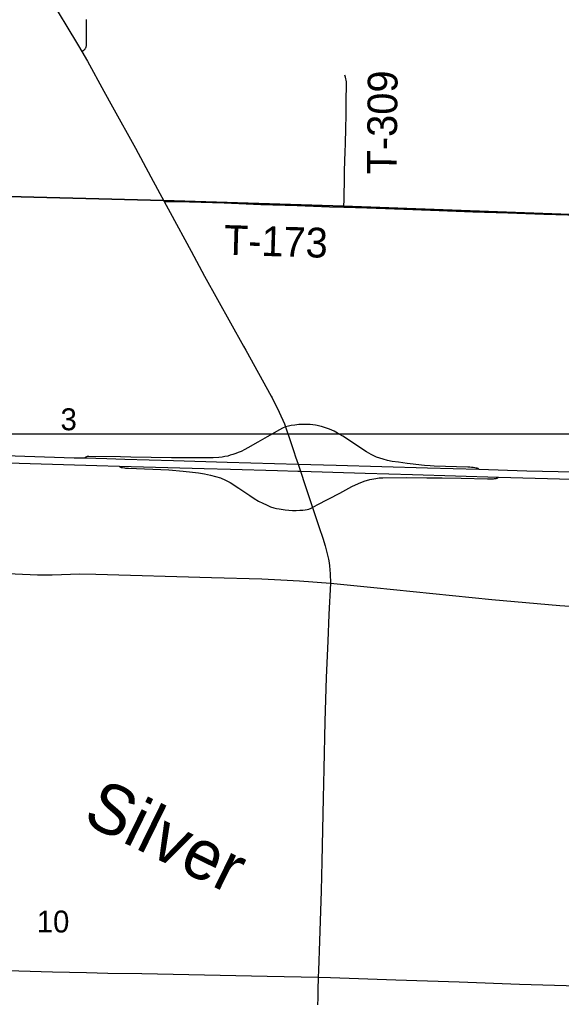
# Model space of a CAD drawing. Extents: x 0 to 68, y 0 to 52.9.
# Drawn here: x 62.532 to 65.265, y 40.611 to 45.541 of the extents above; entities that cross this region are included whole.
import ezdxf

# ---------------------------------------------------------------- set-up
doc = ezdxf.new("R2010")
doc.units = 0
for name, color, linetype in [('Default', 7, 'Continuous'), ('GM_X_County_Road', 7, 'Continuous'), ('GM_X_Minor_River_Text', 7, 'Continuous'), ('GM_X_State_Route', 7, 'Continuous'), ('GM_X_Township', 7, 'Continuous'), ('GM_X_Township_Road', 7, 'Continuous'), ('GM_X_Township_Road_Text', 7, 'Continuous')]:
    doc.layers.add(name, color=color, linetype=linetype)

msp = doc.modelspace()

# ---------------------------------------------------------------- linework, layer by layer
at = {"layer": 'Default'}
msp.add_line((49.5172, 43.4514), (67.9972, 43.4514), dxfattribs=at)
for points in [[(63.8738, 43.4876), (63.8583, 43.4805), (63.8433, 43.4728), (63.7811, 43.4371), (63.7335, 43.4098), (63.6832, 43.3813), (63.6682, 43.3733), (63.6493, 43.3636), (63.6351, 43.3574), (63.623, 43.3524), (63.608, 43.3474), (63.595, 43.3438), (63.582, 43.3403), (63.5676, 43.3372), (63.5537, 43.3347), (63.5369, 43.3327), (63.5077, 43.3308), (63.4405, 43.3305), (63.2985, 43.3315), (63.0932, 43.3352), (63.0407, 43.3361), (62.8818, 43.338), (62.8798, 43.3379), (62.8778, 43.3377), (62.8758, 43.3375), (62.8736, 43.3372), (62.8711, 43.3365), (62.8696, 43.336), (62.8683, 43.3353), (62.8666, 43.3345), (62.8649, 43.3336), (62.8632, 43.3322), (62.862, 43.3306)], [(64.8484, 43.2734), (64.8473, 43.275), (64.8459, 43.2762), (64.8446, 43.2772), (64.8425, 43.2781), (64.8394, 43.279), (64.8349, 43.2798), (64.8279, 43.2808), (64.8204, 43.2819), (64.8117, 43.2829), (64.8031, 43.2836), (64.7932, 43.2841), (64.6226, 43.2892), (64.602, 43.2901), (64.5748, 43.2924), (64.5585, 43.294), (64.5178, 43.2989), (64.4869, 43.3026), (64.4424, 43.3089), (64.4105, 43.3132), (64.3872, 43.3182), (64.366, 43.3241), (64.3489, 43.3294), (64.3329, 43.3353), (64.3057, 43.3471), (64.2821, 43.3615), (64.1621, 43.4402), (64.1353, 43.4561), (64.1185, 43.4659), (64.0952, 43.4757), (64.0691, 43.4847), (64.0556, 43.4885), (64.0465, 43.4909), (64.0332, 43.4937), (64.0249, 43.4951), (64.0112, 43.4974), (63.9972, 43.4985), (63.9789, 43.4994), (63.9621, 43.4996), (63.9406, 43.4985), (63.921, 43.4966), (63.9023, 43.4936), (63.8881, 43.4906), (63.8738, 43.4876)], [(63.0349, 43.2889), (63.0367, 43.2868), (63.0387, 43.2854), (63.0407, 43.2842), (63.0444, 43.2831), (63.0505, 43.282), (63.0614, 43.2803), (63.0666, 43.2798), (63.0751, 43.2789), (63.0821, 43.2785), (63.2851, 43.2708), (63.3568, 43.2647), (63.4043, 43.2594), (63.4341, 43.255), (63.4645, 43.2497), (63.4957, 43.2437), (63.5206, 43.2375), (63.5456, 43.2295), (63.5703, 43.2192), (63.5939, 43.2065), (63.6381, 43.1786), (63.6933, 43.1409), (63.7153, 43.1264), (63.7378, 43.1131), (63.7583, 43.1019), (63.7769, 43.0937), (63.7975, 43.0848), (63.8136, 43.0795), (63.8285, 43.0756), (63.8412, 43.0735), (63.8719, 43.0683), (63.8908, 43.0669), (63.9078, 43.0661), (63.9264, 43.0657), (63.9461, 43.0667), (63.9605, 43.0679), (63.972, 43.0694), (63.9825, 43.0713), (63.9903, 43.0731), (64.0027, 43.0775), (64.0098, 43.0807)], [(64.0098, 43.0807), (64.0324, 43.0937), (64.1476, 43.1536), (64.2081, 43.1865), (64.2418, 43.2022), (64.2702, 43.2135), (64.2993, 43.2217), (64.3285, 43.2277), (64.3462, 43.2299), (64.3636, 43.2307), (64.4824, 43.2315), (64.5856, 43.2305), (64.6634, 43.23), (64.7597, 43.2288), (64.8911, 43.2257), (64.9025, 43.2256), (64.9097, 43.2258), (64.9164, 43.2258), (64.9217, 43.2259), (64.9274, 43.2263), (64.9316, 43.2268), (64.9352, 43.2275), (64.9372, 43.228), (64.9396, 43.2287), (64.9411, 43.2293), (64.9428, 43.2302), (64.9443, 43.2311), (64.9467, 43.2336)]]:
    msp.add_lwpolyline(points, dxfattribs=at)
at = {"layer": 'GM_X_County_Road'}
for points in [[(61.4084, 42.7758), (61.5807, 42.7713), (61.9087, 42.7641), (62.081, 42.7585), (62.4337, 42.7489), (62.6223, 42.7413), (62.6961, 42.7404), (62.8355, 42.7456), (62.9175, 42.7446), (63.4999, 42.728), (63.7542, 42.7209), (63.8505, 42.7161), (63.9445, 42.7111), (64.1003, 42.699)], [(64.1003, 42.699), (64.3192, 42.6776), (64.9136, 42.6174), (65.2569, 42.5872), (65.404, 42.5773)]]:
    msp.add_lwpolyline(points, dxfattribs=at)
at = {"layer": 'GM_X_State_Route'}
for points in [[(62.6505, 45.7038), (62.7654, 45.5142), (62.8292, 45.4088), (62.8462, 45.3801), (62.8747, 45.3308), (62.958, 45.1798), (63.0017, 45.1008), (63.1163, 44.8921), (63.1945, 44.7478), (63.2615, 44.6243), (63.2923, 44.5673), (63.3976, 44.3723), (63.4652, 44.2478), (63.6612, 43.8946)], [(63.6612, 43.8946), (63.6728, 43.8736), (63.8002, 43.6425)], [(63.8002, 43.6425), (63.8054, 43.6331), (63.8418, 43.5616), (63.8687, 43.5025), (63.8738, 43.4876), (63.8956, 43.4241), (63.9156, 43.3625), (63.9242, 43.3369)], [(57.8017, 43.4415), (58.1951, 43.4298), (58.4574, 43.4223), (58.7554, 43.413), (58.9787, 43.4062), (59.143, 43.4019), (59.4533, 43.3942), (59.7567, 43.3852), (60.3554, 43.3677), (60.5933, 43.3608), (60.7655, 43.3564), (61.192, 43.3434), (61.4253, 43.3367), (61.6759, 43.3292), (62.2007, 43.3137), (62.5862, 43.3022), (62.9212, 43.293), (63.0349, 43.2889), (63.4638, 43.2776), (63.5951, 43.2748), (63.8329, 43.2671), (63.9354, 43.2642)], [(62.358, 43.346), (62.8081, 43.3315), (62.862, 43.3306), (62.9728, 43.3285), (63.0636, 43.3248), (63.3087, 43.3175), (63.5789, 43.3096), (63.9367, 43.2994), (64.1295, 43.2937), (64.5892, 43.2808), (64.8484, 43.2734), (65.0899, 43.2658), (65.3279, 43.2601)], [(63.9242, 43.3369), (63.9367, 43.2994), (63.9484, 43.2638), (63.9722, 43.1916), (64.0098, 43.0807), (64.0433, 42.9795), (64.061, 42.9264), (64.0737, 42.8875), (64.082, 42.8531), (64.0895, 42.8203), (64.0929, 42.8012)], [(63.9354, 43.2642), (63.9484, 43.2638), (64.2757, 43.2545), (64.5136, 43.2469), (64.9467, 43.2336), (65.3173, 43.224)], [(64.0929, 42.8012), (64.0954, 42.7874), (64.0992, 42.747), (64.1003, 42.699), (64.0926, 42.5406)], [(64.0926, 42.5406), (64.086, 42.4067), (64.0778, 42.2228), (64.0716, 42.0013), (64.0658, 41.7633), (64.0638, 41.6156), (64.0565, 41.2956), (64.0523, 41.148), (64.0444, 40.8936), (64.0394, 40.746), (64.0385, 40.7129), (64.0369, 40.6475), (64.0341, 40.5327)]]:
    msp.add_lwpolyline(points, dxfattribs=at)
at = {"layer": 'GM_X_Township'}
for points in [[(67.9972, 44.4735), (67.0472, 44.4994), (66.7919, 44.503), (65.491, 44.5506), (64.1656, 44.6005), (63.2588, 44.629), (61.4939, 44.6747), (60.178, 44.6988), (58.8701, 44.7399), (58.8342, 44.7404), (56.8623, 44.7881)], [(56.8623, 44.7881), (58.8342, 44.7404), (58.8701, 44.7399), (60.178, 44.6988), (61.4939, 44.6747), (63.2588, 44.629), (64.1656, 44.6005), (65.491, 44.5506), (66.7919, 44.503), (66.7384, 42.9192), (66.7226, 42.4208), (66.6973, 41.2859), (66.6815, 40.6291), (66.6161, 37.9756), (66.5723, 36.6564), (66.5449, 35.3382), (66.5266, 34.4614)]]:
    msp.add_lwpolyline(points, dxfattribs=at)
at = {"layer": 'GM_X_Township_Road'}
for points in [[(62.8462, 45.3801), (62.8536, 45.3847), (62.8579, 45.3877), (62.8599, 45.3895), (62.8624, 45.3919), (62.8635, 45.3932), (62.8652, 45.3957), (62.8662, 45.3974), (62.8672, 45.3998), (62.8679, 45.402), (62.8685, 45.405), (62.869, 45.409), (62.8693, 45.4138), (62.8693, 45.4195), (62.8698, 45.438), (62.8698, 45.4474), (62.87, 45.4824), (62.8706, 45.5412)], [(64.1679, 44.5952), (64.1682, 44.6087), (64.1684, 44.624), (64.1713, 44.7597), (64.1732, 44.8451), (64.1734, 44.8566), (64.1744, 44.8845), (64.1751, 44.9042), (64.1762, 44.9354), (64.1772, 44.9715), (64.1787, 45.0783), (64.1798, 45.1456), (64.1808, 45.1981), (64.181, 45.2107), (64.1801, 45.2271), (64.1793, 45.2348), (64.1782, 45.2416), (64.1759, 45.2503), (64.1732, 45.2599)], [(63.2615, 44.6243), (63.3297, 44.623), (63.5641, 44.6162), (63.7488, 44.6088), (63.9325, 44.6031), (64.0943, 44.5973), (64.1679, 44.5952)], [(64.1679, 44.5952), (64.2829, 44.591), (64.4697, 44.5846), (64.6479, 44.5783), (64.8177, 44.572), (64.9942, 44.5661), (65.1767, 44.5602), (65.3576, 44.5543), (65.4637, 44.5506), (65.4928, 44.5488)], [(61.359, 40.7805), (61.7217, 40.7698), (62.0744, 40.7583), (62.6978, 40.7396), (62.8701, 40.7359), (62.9768, 40.7333), (63.1491, 40.7307), (63.7809, 40.7182), (64.0385, 40.7129)], [(64.0385, 40.7129), (64.1009, 40.7116), (64.429, 40.7), (64.7489, 40.689), (65.0524, 40.6782), (65.3476, 40.6687), (65.741, 40.6557), (66.4547, 40.6317), (66.6433, 40.6249), (66.6679, 40.6239), (66.6831, 40.6232)]]:
    msp.add_lwpolyline(points, dxfattribs=at)

# ---------------------------------------------------------------- texts
at = {"layer": 'Default'}
for s, p in [('3', (62.7389, 43.4702)), ('10', (62.619, 40.9381))]:
    msp.add_text(s, height=0.1105, rotation=0, dxfattribs=at).set_placement(p)
at = {"layer": 'GM_X_Minor_River_Text'}
msp.add_text('Silver', height=0.2501, rotation=333.8764, dxfattribs=at).set_placement((62.8433, 41.4952))
at = {"layer": 'GM_X_Township_Road_Text'}
for s, rotation, p in [('T-309', 89.4372, (64.4336, 44.7594)), ('T-173', 358.3152, (63.5606, 44.355))]:
    msp.add_text(s, height=0.15, rotation=rotation, dxfattribs=at).set_placement(p)

doc.saveas('drawing.dxf')
